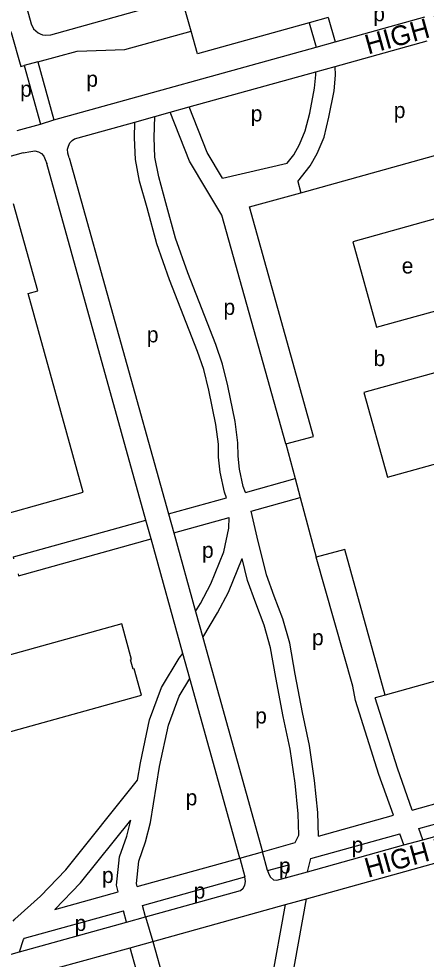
# Model space of a CAD drawing. Extents: x 158358 to 160383, y 379531 to 380764.
# Drawn here: x 160024.2 to 160128, y 380237.9 to 380477.3 of the extents above; entities that cross this region are included whole.
import ezdxf

# ---------------------------------------------------------------- set-up
doc = ezdxf.new("R2010")
doc.units = 0
for name, color, linetype in [('BLT_Basislijn', 7, 'Continuous'), ('BLT_Bebouwing', 7, 'Continuous'), ('BLT_Centroide', 7, 'Continuous'), ('BLT_Straatnaam', 7, 'Continuous'), ('BLT_Vlakafsluiter', 7, 'Continuous')]:
    doc.layers.add(name, color=color, linetype=linetype)

msp = doc.modelspace()

# ---------------------------------------------------------------- linework, layer by layer
at = {"layer": 'BLT_Basislijn'}
for p, q in [((160098.17, 380476.33), (160099.95, 380470.14)), ((160102.98, 380477.67), (160104.77, 380471.48)), ((160029.03, 380466.37), (160025.57, 380465.43)), ((160029.03, 380466.37), (160033.1, 380451.59)), ((160025.57, 380465.43), (160029.69, 380450.52)), ((160029.69, 380450.52), (160033.1, 380451.59)), ((160092.25, 380369.1), (160075.93, 380427.38)), ((160081.95, 380356.73), (160094.61, 380360.26)), ((160062.34, 380351.28), (160077.11, 380355.39)), ((160083.43, 380351.96), (160095.9, 380355.42)), ((160063.68, 380346.46), (160077.8, 380350.39)), ((160117.53, 380305.15), (160115.01, 380304.45)), ((160124.46, 380275.87), (160200.67, 380297.06)), ((160126.15, 380271.15), (160202, 380292.24)), ((160100.52, 380269.22), (160119.63, 380274.53)), ((160098.6, 380263.5), (160121.32, 380269.81)), ((160086.25, 380265.25), (160094.64, 380267.58)), ((160087.59, 380260.44), (160086.25, 380265.25)), ((160054.36, 380256.39), (160080.47, 380263.65)), ((160080.47, 380263.65), (160081.81, 380258.83)), ((160087.59, 380260.44), (160093.03, 380261.95)), ((160055.68, 380251.57), (160081.81, 380258.83)), ((160033.4, 380250.56), (160049.55, 380255.05)), ((160025.67, 380243.22), (160050.86, 380250.23)), ((160058.34, 380242.42), (160063.94, 380222.35)), ((160033.96, 380235.66), (160052.56, 380240.82)), ((160054.18, 380235.02), (160052.56, 380240.82))]:
    msp.add_line(p, q, dxfattribs=at)
for points in [[(160021.81, 380496.07), (160027.37, 380476.05), (160027.97, 380474.83), (160028.49, 380474.26), (160029.15, 380473.74), (160029.64, 380473.49), (160030.2, 380473.3), (160030.98, 380473.15), (160032.36, 380473.3), (160060.95, 380481.22)], [(160104.77, 380471.48), (160127.67, 380477.83)], [(160021.01, 380474.58), (160021.43, 380474.61), (160021.79, 380474.49), (160022.09, 380474.23), (160022.25, 380473.9), (160024.68, 380465.19), (160025.57, 380465.43)], [(160029.03, 380466.37), (160039.1, 380469.11), (160051.24, 380469.52), (160068.1, 380474.19)], [(160099.95, 380470.14), (160104.77, 380471.48)], [(160104.8, 380465.23), (160128.21, 380471.73)], [(160033.1, 380451.59), (160099.95, 380470.14)], [(160067.58, 380454.89), (160099.86, 380463.86)], [(160092.56, 380440.56), (160094.24, 380442.71), (160095.72, 380445.3), (160097.2, 380448.78), (160098.32, 380453.35), (160099.57, 380459.69), (160099.89, 380463.1), (160099.86, 380463.86)], [(160095.28, 380435.92), (160098.4, 380439.91), (160100.21, 380443.08), (160101.96, 380447.2), (160103.21, 380452.27), (160104.53, 380458.97), (160104.9, 380462.99), (160104.8, 380465.23)], [(160099.86, 380463.86), (160104.8, 380465.23)], [(160062.73, 380453.54), (160067.58, 380454.89)], [(160076.09, 380436.8), (160072.17, 380443.3), (160067.58, 380454.89)], [(160053.78, 380451.05), (160058.83, 380452.46)], [(160081.95, 380356.73), (160081.38, 380358.23), (160080.42, 380362.64), (160080.1, 380366.01), (160080.03, 380369.41), (160079.33, 380374.84), (160077.47, 380383.89), (160076.13, 380389.42), (160074.43, 380394.39), (160067.28, 380412.65), (160064.14, 380421.52), (160061.67, 380430.52), (160059.84, 380437.11), (160058.89, 380442.13), (160058.65, 380447.08), (160058.83, 380452.46)], [(160058.83, 380452.46), (160062.73, 380453.54)], [(160075.93, 380427.38), (160072.09, 380433.75), (160067.67, 380441.07), (160062.73, 380453.54)], [(160023.81, 380448.89), (160029.69, 380450.52)], [(160039.32, 380447.04), (160053.78, 380451.05)], [(160077.11, 380355.39), (160076.58, 380356.81), (160075.47, 380361.87), (160075.1, 380365.73), (160075.04, 380369.04), (160074.39, 380374.02), (160072.59, 380382.8), (160071.32, 380388.02), (160069.73, 380392.67), (160062.59, 380410.9), (160059.37, 380420.02), (160056.86, 380429.19), (160054.97, 380435.97), (160053.91, 380441.55), (160053.65, 380447.04), (160053.78, 380451.05)], [(160036.98, 380441.96), (160036.72, 380443.1), (160036.63, 380444.13), (160036.81, 380444.95), (160037.23, 380445.74), (160037.78, 380446.33), (160038.41, 380446.75), (160039.32, 380447.04)], [(160025.27, 380443.18), (159931.55, 380417.09)], [(160025.27, 380443.18), (160027.26, 380443.59), (160028.24, 380443.7), (160029.2, 380443.5), (160029.95, 380443.07), (160030.56, 380442.38), (160030.92, 380441.53), (160031.3, 380440.51)], [(160056.55, 380349.72), (160031.3, 380440.51)], [(160036.98, 380441.96), (160062.34, 380351.28)], [(160076.09, 380436.8), (160092.56, 380440.56)], [(160095.28, 380435.92), (160096.07, 380433.07)], [(160062.34, 380351.28), (160063.68, 380346.46)], [(160100.52, 380269.22), (160100.38, 380275.21), (160099.57, 380283.37), (160098.22, 380292.27), (160096.5, 380300.68), (160094.63, 380310.49), (160093.24, 380318.35), (160091.43, 380324.52), (160089.28, 380330.3), (160087.27, 380335.79), (160084.91, 380345.38), (160083.43, 380351.96)], [(160022.94, 380339.83), (160022.8, 380340.34), (160056.55, 380349.72)], [(160057.89, 380344.91), (160056.55, 380349.72)], [(160069.24, 380326.46), (160070.45, 380328.49), (160073.09, 380333.49), (160076.4, 380341.64), (160077.67, 380347.62), (160077.8, 380350.39)], [(160063.68, 380346.46), (160069.24, 380326.46)], [(160024, 380336.04), (160024.14, 380335.53), (160057.89, 380344.91)], [(160066, 380315.7), (160057.89, 380344.91)], [(160071.09, 380319.8), (160074.82, 380326.05), (160077.62, 380331.38), (160081.1, 380339.93)], [(160094.64, 380267.58), (160095.51, 380269.48), (160095.38, 380274.9), (160094.61, 380282.75), (160093.3, 380291.39), (160091.59, 380299.71), (160089.71, 380309.59), (160088.36, 380317.21), (160086.69, 380322.94), (160084.59, 380328.57), (160082.48, 380334.33), (160081.1, 380339.93)], [(160109.97, 380303.79), (160109.29, 380307.39), (160099.96, 380340.23)], [(160069.24, 380326.46), (160071.09, 380319.8)], [(160071.09, 380319.8), (160086.25, 380265.25)], [(160054.43, 380283.44), (160055.17, 380287.91), (160057.53, 380298.85), (160060.51, 380307.06), (160065.03, 380314.51), (160066, 380315.7)], [(160067.76, 380309.38), (160066, 380315.7)], [(160054.36, 380256.39), (160054.15, 380257.15), (160054.77, 380262.88), (160056.51, 380267.81), (160057.75, 380272.73), (160060.08, 380286.98), (160062.34, 380297.46), (160065.04, 380304.89), (160067.76, 380309.38)], [(160080.47, 380263.65), (160067.76, 380309.38)], [(160119.63, 380274.53), (160115.91, 380284.91), (160109.97, 380303.79)], [(160124.46, 380275.87), (160120.65, 380286.51), (160115.01, 380304.45)], [(160127.16, 380268.32), (160200.86, 380288.81), (160201.73, 380289.38), (160202.17, 380290.25), (160202.15, 380291.19), (160202, 380292.24)], [(160022.76, 380247.6), (160023.14, 380248.08), (160029.71, 380253.93), (160036.19, 380260.62), (160054.43, 380283.44)], [(160033.4, 380250.56), (160039.95, 380257.31), (160052.73, 380273.3)], [(160049.55, 380255.05), (160049.08, 380256.75), (160049.86, 380263.99), (160051.72, 380269.25), (160052.73, 380273.3)], [(160122.33, 380266.98), (160121.32, 380269.81)], [(160127.16, 380268.32), (160126.15, 380271.15)], [(160097.49, 380253.26), (160149.75, 380267.74)], [(160122.33, 380266.98), (160127.16, 380268.32)], [(160097.72, 380260.14), (160122.33, 380266.98)], [(160097.72, 380260.14), (160098.6, 380263.5)], [(160087.59, 380260.44), (160087.9, 380259.53), (160088.3, 380258.74), (160089.09, 380258.08), (160089.96, 380257.98), (160092.15, 380258.59)], [(160092.15, 380258.59), (160093.03, 380261.95)], [(160056.47, 380248.67), (160080.69, 380255.4), (160081.36, 380255.97), (160081.79, 380256.71), (160081.95, 380257.69), (160081.81, 380258.83)], [(160092.15, 380258.59), (160097.72, 380260.14)], [(160092.15, 380251.78), (160097.49, 380253.26)], [(160093.39, 380230.48), (160093.43, 380230.67), (160097.49, 380253.26)], [(160056.47, 380248.67), (160055.68, 380251.57)], [(160058.34, 380242.42), (160092.15, 380251.78)], [(160087.85, 380228.59), (160088.53, 380231.65), (160092.15, 380251.78)], [(160051.66, 380247.33), (160050.86, 380250.23)], [(160051.66, 380247.33), (160056.47, 380248.67)], [(160024.38, 380239.75), (160051.66, 380247.33)], [(160024.38, 380239.75), (160025.4, 380242.89), (160025.67, 380243.22)], [(160052.56, 380240.82), (160058.34, 380242.42)], [(160018.59, 380238.14), (160024.38, 380239.75)]]:
    msp.add_lwpolyline(points, dxfattribs=at)
at = {"layer": 'BLT_Bebouwing'}
for p, q in [((160092.25, 380369.1), (160094.61, 380360.26)), ((160094.61, 380360.26), (160095.9, 380355.42)), ((160095.9, 380355.42), (160099.96, 380340.23))]:
    msp.add_line(p, q, dxfattribs=at)
for points in [[(160068.1, 380474.19), (160065.77, 380482.56)], [(160098.17, 380476.33), (160069.7, 380468.42), (160068.1, 380474.19)], [(160102.98, 380477.67), (160098.17, 380476.33)], [(160096.07, 380433.07), (160135.64, 380444.06)], [(160082.98, 380429.43), (160096.07, 380433.07)], [(160010.88, 380348.51), (160040.63, 380356.77), (160026.61, 380407.38), (160029.01, 380408.05), (160022.85, 380430.21)], [(160092.25, 380369.1), (160099.24, 380370.96), (160082.98, 380429.43)], [(160130.88, 380426.57), (160109.28, 380420.57), (160115.32, 380398.81), (160136.91, 380404.8), (160130.88, 380426.57)], [(160140.93, 380390.19), (160112.1, 380382.2), (160118.1, 380360.6), (160146.93, 380368.58), (160140.93, 380390.19)], [(160117.53, 380305.15), (160107.24, 380342.17), (160099.96, 380340.23)], [(159970.47, 380281.52), (160055.47, 380305.1), (160053.61, 380311.8), (160053.36, 380311.73), (160052.69, 380314.13), (160052.94, 380314.2), (160050.41, 380323.28)], [(160050.41, 380323.28), (160020.18, 380314.87)], [(160171.69, 380320.19), (160117.53, 380305.15)]]:
    msp.add_lwpolyline(points, dxfattribs=at)
at = {"layer": 'BLT_Vlakafsluiter'}
for p, q in [((160080.47, 380263.65), (160086.25, 380265.25)), ((160056.47, 380248.67), (160058.34, 380242.42))]:
    msp.add_line(p, q, dxfattribs=at)

# ---------------------------------------------------------------- texts
at = {"layer": 'BLT_Centroide'}
for s, p in [('p', (160114.51, 380476.72)), ('p', (160041.39, 380460.05)), ('p', (160024.54, 380457.5)), ('p', (160083.29, 380451.22)), ('p', (160119.74, 380452.07)), ('e', (160121.77, 380412.49)), ('p', (160076.35, 380401.95)), ('p', (160056.82, 380394.95)), ('b', (160114.59, 380388.9)), ('p', (160070.87, 380340.07)), ('p', (160098.91, 380317.82)), ('p', (160084.42, 380297.9)), ('p', (160066.71, 380277.06)), ('p', (160109, 380265.02)), ('p', (160090.5, 380259.69)), ('p', (160045.4, 380257.29)), ('p', (160068.75, 380253.32)), ('p', (160038.42, 380245.08))]:
    msp.add_text(s, height=4, dxfattribs=at).set_placement(p)
at = {"layer": 'BLT_Straatnaam'}
for p in [(160113.2, 380468.25), (160113.14, 380258.59)]:
    msp.add_text('HIGH TECH CAMPUS', height=5, rotation=15.534, dxfattribs=at).set_placement(p)

doc.saveas('drawing.dxf')
